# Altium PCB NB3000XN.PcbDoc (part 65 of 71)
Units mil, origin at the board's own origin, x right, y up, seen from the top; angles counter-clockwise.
Board outline 9527.56 x 6929.77 mil, 6 copper layers (Top Layer, GND+SHIELD, MidLayer1, MidLayer2, P2 - 3V3+5V0, Bottom Layer), stack 62.375 mil thick; 832 components, 1027 nets, 4655 pads, 4981 vias.
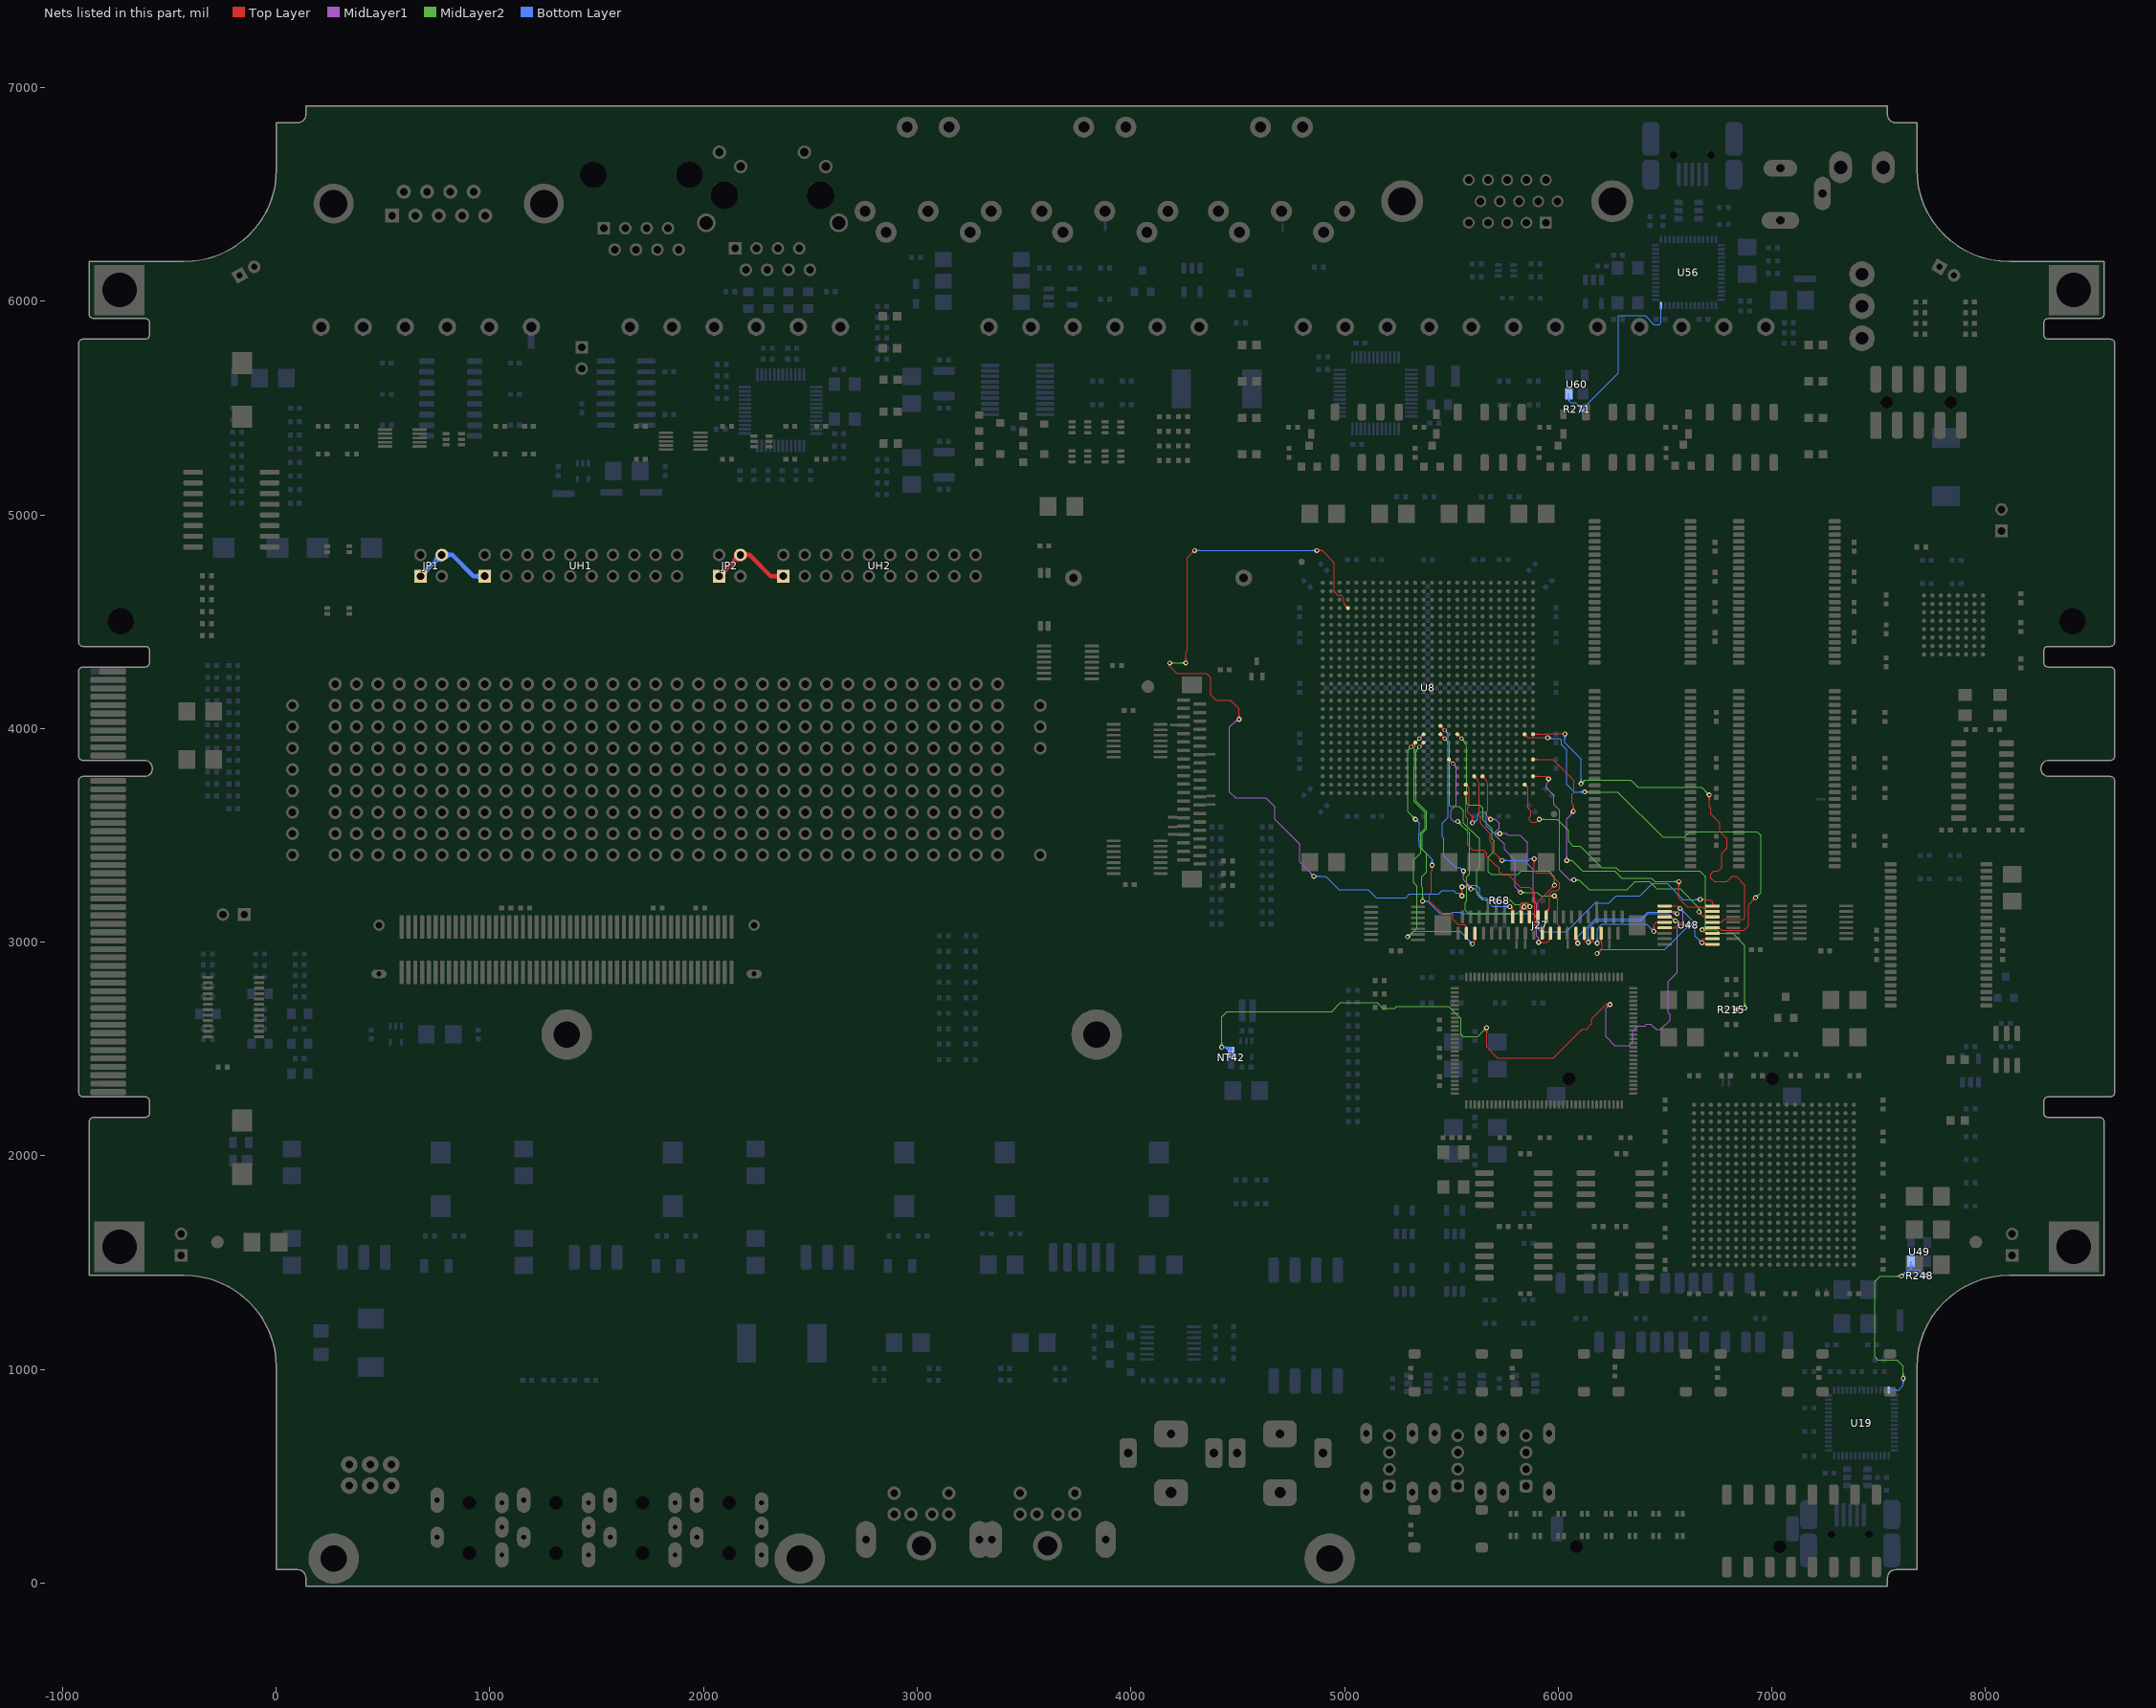
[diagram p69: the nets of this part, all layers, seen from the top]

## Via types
v1: diameter 23, hole 11.81, Top Layer to Bottom Layer, 3672 vias
v2: diameter 26, hole 11.81, Top Layer to Bottom Layer, 461 vias
v3: diameter 19, hole 11.81, Top Layer to Bottom Layer, tented both sides, 396 vias
v4: diameter 23.62, hole 11.81, Top Layer to Bottom Layer, 288 vias
v5: diameter 20, hole 11.81, Top Layer to Bottom Layer, 91 vias
v6: diameter 23, hole 11.81, Top Layer to Bottom Layer, tented both sides, 50 vias
v7: diameter 31, hole 11.81, Top Layer to Bottom Layer, 15 vias
v8: diameter 27.56, hole 11.81, Top Layer to Bottom Layer, tented both sides, 4 vias
v9: diameter 29, hole 11.81, Top Layer to Bottom Layer, 3 vias
v10: diameter 21, hole 11.81, Top Layer to Bottom Layer, 1 vias

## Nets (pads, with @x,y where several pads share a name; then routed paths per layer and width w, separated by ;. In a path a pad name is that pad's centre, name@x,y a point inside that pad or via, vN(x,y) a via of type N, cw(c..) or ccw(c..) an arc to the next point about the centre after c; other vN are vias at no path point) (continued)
TFT_IO.DB14: J27.19 U8.AD19 | length 1217.8
  Top Layer w4: U8.AD19@5606.54,3769.27 cw(c5606.54,3751.55) 5619.07,3764.08 ; U8.AD19@5613.88,3776.61 ccw(c5631.6,3776.61) 5619.07,3764.08 ; v1@5727.36,3382.37 ccw(c5704.42,3382.37) 5720.64,3398.59 ccw(c5736.86,3414.81) v1@5736.86,3391.87 ; v1@5731.36,3382.37 ccw(c5718.08,3382.37) 5727.47,3391.76 ccw(c5736.86,3401.15) v1@5736.86,3387.87 ; v1(5736.86,3382.37) 5691.19,3428.04 5691.19,3463.37 5682.86,3471.71 5682.86,3507.14 5636,3554 5636,3585.19 5630.4,3590.79 5630.4,3599 5630.4,3660 5630.4,3670 5630.4,3736.73 ccw(c5591.72,3736.73) 5619.07,3764.08 ; v1@5881.14,3383.99 cw(c5864.92,3367.77) 5887.86,3367.77 cw(c5910.79,3367.77) v1@5894.57,3383.99 ; v1@5883.97,3386.82 cw(c5874.58,3377.43) 5887.86,3377.43 cw(c5901.14,3377.43) v1@5891.75,3386.82 ; v1(5887.86,3390.71) 5887.86,3335.71 5898.52,3325.04 5956.86,3325.04 6006.86,3275.04 6006.86,3251.71 5996.86,3241.71 5973.52,3241.71 5960,3228.18 5960,3160 5944.95,3144.95 J27.19@5944.95,3118.39 ; J27.19@5946.82,3140.51 cw(c5962.05,3140.51) 5951.28,3151.28 ; J27.19@5950.82,3140.51 cw(c5975.71,3140.51) 5958.11,3158.11
  Bottom Layer w4: v1(5736.86,3382.37) 5859.96,3382.37 5868.29,3390.71 v1(5887.86,3390.71) 5887.86,3385.04 v1@5885.19,3382.37 ; v1@5740.75,3378.49 cw(c5750.14,3369.1) 5750.14,3382.37 cw(c5750.14,3395.65) v1@5740.75,3386.26 ; v1@5743.57,3375.66 cw(c5759.79,3359.44) 5759.79,3382.37 cw(c5759.79,3405.31) v1@5743.57,3389.09
TFT_IO.DB15: J27.21 U8.W17 | length 1570.7
  Top Layer w4: U8.W17@5527.8,3965.96 cw(c5527.8,3947.86) 5540.6,3960.66 cw(c5553.4,3973.46) U8.W17@5535.3,3973.46 ; U8.W17@5527.8,3966.12 cw(c5527.8,3948.4) 5540.33,3960.93 cw(c5552.86,3973.46) U8.W17@5535.14,3973.46 ; U8.W17@5527.8,3973.46 v3(5547.48,3953.78) ; J27.21@5901.42,3144.67 ccw(c5891.4,3154.69) 5905.58,3154.69 ccw(c5919.76,3154.69) J27.21@5909.73,3144.67 ; J27.21@5905.58,3118.39 5905.58,3189.43 v1(5982.86,3266.71) ; v1@5973.36,3266.71 cw(c5950.42,3266.71) 5966.64,3250.49 cw(c5982.86,3234.27) v1@5982.86,3257.21 ; v1@5977.36,3266.71 cw(c5964.08,3266.71) 5973.47,3257.32 cw(c5982.86,3247.93) v1@5982.86,3261.21 ; 5534.68,3966.58 cw(c5521.87,3953.78) 5539.98,3953.78 ccw(c5521.87,3953.78) 5534.68,3966.58 ; 5534.68,3966.58 ccw(c5547.48,3979.39) 5547.48,3961.28 cw(c5547.48,3979.39) 5534.68,3966.58
  MidLayer2 w4: v3@5546.83,3946.31 cw(c5545.25,3928.27) 5559.12,3939.91 ; v3@5554.95,3953.13 ccw(c5572.99,3951.55) 5559.12,3939.91 ; 5571.34,3680.84 5571.34,3739.1 ; v1(5982.86,3266.71) 5982.86,3307.14 5956.63,3333.37 5827.86,3333.37 5811.19,3316.71 5685.48,3316.71 5672.19,3330 5672.19,3398.04 5699.19,3425.04 5699.19,3475.04 5690.86,3483.37 5690.86,3530.02 5648.52,3572.35 5648.52,3600 5648.52,3625.71 5631.86,3642.37 5577.63,3642.37 5571.34,3648.66 5571.34,3660 5571.34,3670 5571.34,3739.1 ; 5559.12,3939.91 cw(c5529.61,3910.4) 5571.34,3910.4 5571.34,3890.9 5571.34,3816.78 5571.34,3797.36 5571.34,3739.1
TFT_IO.DB16: J27.23 U8.AB16 | length 1499.3
  Top Layer w4: U8.AB16@5488.43,3847.85 cw(c5488.43,3829.75) 5501.23,3842.55 cw(c5514.03,3855.35) U8.AB16@5495.93,3855.35 ; U8.AB16@5488.43,3848.01 cw(c5488.43,3830.29) 5500.96,3842.82 cw(c5513.49,3855.35) U8.AB16@5495.77,3855.35 ; U8.AB16@5488.43,3855.35 v3(5508.11,3835.67) ; v1@5840.19,3156.21 cw(c5840.19,3133.27) 5856.41,3149.49 cw(c5872.63,3165.71) v1@5849.69,3165.71 ; v1@5840.19,3160.21 cw(c5840.19,3146.93) 5849.58,3156.32 cw(c5858.97,3165.71) v1@5845.69,3165.71 ; v1(5840.19,3165.71) 5866.21,3139.69 J27.23@5866.21,3118.39 ; 5854.78,3151.12 ccw(c5866.21,3162.55) J27.23@5866.21,3146.39 ; 5856.76,3149.14 cw(c5848.13,3140.51) J27.23@5860.33,3140.51 ; 5495.31,3848.47 cw(c5482.5,3835.67) 5500.61,3835.67 ccw(c5482.5,3835.67) 5495.31,3848.47 ; 5495.31,3848.47 ccw(c5508.11,3861.28) 5508.11,3843.17 cw(c5508.11,3861.28) 5495.31,3848.47
  MidLayer1 w4: 5498.5,3604.17 5498.5,3601.75 ; v3@5507.46,3828.2 cw(c5505.88,3810.16) 5519.75,3821.8 cw(c5533.62,3833.44) v3@5515.58,3835.02 ; 5517.88,3565.37 cw(c5517.88,3555.43) v1@5525.68,3561.59 ; 5519.5,3822.09 cw(c5509.57,3812.16) 5523.62,3812.16 5523.62,3718.62 5523.62,3670 5523.62,3660 5523.62,3650.04 ; v1@5522.54,3559.11 ccw(c5509.63,3548.92) 5509.63,3565.37 ; v1@5522.91,3571.33 cw(c5509.63,3583.18) 5509.63,3565.37 ; 5523.52,3650.04 5523.52,3644.37 5497.5,3618.35 5497.5,3602.75 5498.5,3601.75 ; v1@5530,3565.37 5509.63,3565.37 ; 5498.5,3601.75 5498.5,3576.5 5509.63,3565.37
  MidLayer2 w4: v1@5530,3555.5 cw(c5530,3532.56) 5546.22,3548.78 cw(c5562.43,3565) v1@5539.5,3565 ; v1@5530,3559.5 cw(c5530,3546.22) 5539.39,3555.61 cw(c5548.78,3565) v1@5535.5,3565 ; v1@5531.86,3565 5531.86,3565.37 5531.48,3565 v1(5530,3565) 5585,3510 5585,3319.75 5572.5,3307.25 5572.5,3193.02 5565.19,3185.71 5565.19,3150.04 5581.86,3133.37 5807.86,3133.37 v1(5840.19,3165.71) ; v1@5830.69,3165.71 cw(c5807.76,3165.71) 5823.97,3149.49 cw(c5840.19,3133.27) v1@5840.19,3156.21 ; v1@5834.69,3165.71 cw(c5821.41,3165.71) 5830.8,3156.32 cw(c5840.19,3146.93) v1@5840.19,3160.21
TFT_IO.DB17: J27.25 U8.W15 | length 1532.1
  Top Layer w4: U8.W15@5449.06,3965.96 cw(c5449.06,3947.86) 5461.86,3960.66 cw(c5474.66,3973.46) U8.W15@5456.56,3973.46 ; U8.W15@5449.06,3966.12 cw(c5449.06,3948.4) 5461.59,3960.93 cw(c5474.12,3973.46) U8.W15@5456.4,3973.46 ; U8.W15@5449.06,3973.46 v3(5468.74,3953.78) ; J27.25@5822.76,3144.75 ccw(c5813.56,3154.31) 5826.84,3154.31 ; J27.25@5826.84,3118.39 5826.84,3154.31 ; J27.25@5830.91,3144.75 cw(c5840.11,3154.31) 5826.84,3154.31 ; 5859.36,3183.21 cw(c5849.77,3173.63) v1@5862.4,3168.71 ; 5863.69,3178.88 cw(c5856.01,3171.2) v1@5866.13,3167.25 ; v1(5867.52,3166.71) 5867.52,3175.04 5859.19,3183.37 5831.86,3183.37 5822.69,3174.21 5822.69,3158.46 5826.84,3154.31 ; 5455.94,3966.58 cw(c5443.13,3953.78) 5461.24,3953.78 ccw(c5443.13,3953.78) 5455.94,3966.58 ; 5455.94,3966.58 ccw(c5468.74,3979.39) 5468.74,3961.28 cw(c5468.74,3979.39) 5455.94,3966.58
  MidLayer2 w4: v3@5468.09,3946.31 cw(c5466.51,3928.27) 5480.38,3939.91 ; v3@5476.21,3953.13 ccw(c5494.25,3951.55) 5480.38,3939.91 ; 5492.6,3680.84 5492.6,3739.1 ; v1@5858.02,3166.71 ccw(c5835.09,3166.71) 5851.31,3182.93 ccw(c5867.52,3199.14) v1@5867.52,3176.21 ; v1@5862.02,3166.71 ccw(c5848.75,3166.71) 5858.14,3176.1 ccw(c5867.52,3185.49) v1@5867.52,3172.21 ; v1(5867.52,3166.71) 5850.86,3183.37 5830,3183.37 5823.33,3176.71 5796.86,3176.71 5773.52,3200.04 5648.52,3200.04 5619.5,3229.06 5619.5,3337.68 5631.86,3350.04 5631.86,3483.37 5556.86,3558.37 5556.86,3616.04 5556.53,3616.37 5536.9,3636 5496.6,3636 5492.6,3640 5492.6,3660 5492.6,3670 5492.6,3739.1 ; 5480.38,3939.91 cw(c5450.87,3910.4) 5492.6,3910.4 5492.6,3890.9 5492.6,3816.78 5492.6,3797.36 5492.6,3739.1
TFT_IO.IR38KRX: J27.36 U8.W13 | length 1741.3
  Top Layer w4: v3(5350.63,3953.78) U8.W13@5370.31,3973.46 ; U8.W13@5362.81,3973.46 cw(c5344.71,3973.46) 5357.51,3960.66 cw(c5370.31,3947.86) U8.W13@5370.31,3965.96 ; U8.W13@5362.97,3973.46 cw(c5345.25,3973.46) 5357.78,3960.93 cw(c5370.31,3948.4) U8.W13@5370.31,3966.12 ; v1(5598.52,2991.71) 5610.3,3003.48 J27.36@5610.3,3041.61 ; J27.36@5606.15,3015.33 cw(c5596.12,3005.31) 5610.3,3005.31 cw(c5624.48,3005.31) J27.36@5614.45,3015.33 ; 5363.43,3966.58 ccw(c5376.24,3953.78) 5358.13,3953.78 cw(c5376.24,3953.78) 5363.43,3966.58 ; 5363.43,3966.58 cw(c5350.63,3979.39) 5350.63,3961.28 ccw(c5350.63,3979.39) 5363.43,3966.58
  MidLayer2 w4: v1(5295,3025) 5298.48,3025 5298.52,3025.04 5340.19,3066.71 5340.19,3261.35 5322.52,3279.02 5322.52,3385.04 5356.7,3419.22 5356.7,3513.31 5377,3533.61 5377,3607.31 5326.77,3657.55 5326.77,3660 5326.77,3670 5326.77,3797.36 5326.77,3816.78 5326.77,3890.9 5326.77,3910.4 cw(c5368.5,3910.4) 5338.99,3939.91 ; v1@5295,3030.5 ccw(c5295,3052.19) 5310.34,3036.85 ; v1@5295,3034.5 ccw(c5295,3065.84) 5317.16,3043.68 ; v1@5304.5,3025 cw(c5319.03,3025) 5308.75,3035.27 ; v3@5343.16,3953.13 cw(c5325.12,3951.55) 5338.99,3939.91 ; v3@5351.28,3946.31 ccw(c5352.86,3928.27) 5338.99,3939.91
  Bottom Layer w4: v1(5295,3025) 5320.37,3050.37 5539.86,3050.37 v1(5598.52,2991.71) ; v1@5295,3030.5 ccw(c5295,3043.78) 5304.39,3034.39 ccw(c5313.78,3025) v1@5300.5,3025 ; v1@5295,3034.5 ccw(c5295,3057.43) 5311.22,3041.22 ccw(c5327.43,3025) v1@5304.5,3025 ; v1@5589.02,2991.71 ccw(c5566.09,2991.71) 5582.31,3007.93 ccw(c5598.52,3024.14) v1@5598.52,3001.21 ; v1@5593.02,2991.71 ccw(c5579.75,2991.71) 5589.14,3001.1 ccw(c5598.52,3010.49) v1@5598.52,2997.21
TFT_IO.IR38KTX: J27.38 U8.Y12 | length 1411.3
  Top Layer w4: v3(5311.26,3914.41) U8.Y12@5330.94,3934.09 ; U8.Y12@5323.44,3934.09 cw(c5305.34,3934.09) 5318.14,3921.29 cw(c5330.94,3908.49) U8.Y12@5330.94,3926.59 ; U8.Y12@5323.6,3934.09 cw(c5305.88,3934.09) 5318.41,3921.56 cw(c5330.94,3909.03) U8.Y12@5330.94,3926.75 ; v1(5410,3360) 5410,3334.96 5406,3330.96 5406,3232.52 5398.52,3225.04 5398.52,3191.71 5456.86,3133.37 5505.19,3133.37 5506.86,3131.71 5506.86,3107.04 5531.86,3082.04 5560.34,3082.04 5570.93,3071.45 J27.38@5570.93,3041.61 ; 5562.95,3079.44 cw(c5548.16,3064.65) J27.38@5569.06,3063.81 ; 5569.41,3072.97 cw(c5560.59,3064.15) J27.38@5573.06,3063.66 ; 5324.06,3927.21 cw(c5311.26,3940.02) 5311.26,3921.91 ccw(c5311.26,3940.02) 5324.06,3927.21 ; 5324.06,3927.21 ccw(c5336.87,3914.41) 5318.76,3914.41 cw(c5336.87,3914.41) 5324.06,3927.21
  MidLayer2 w4: 5295.75,3876.97 5295.75,3890.9 ; 5299.87,3900.83 ccw(c5309.8,3890.9) 5295.75,3890.9 ; v3@5303.79,3913.76 cw(c5285.75,3912.18) 5299.62,3900.54 cw(c5313.49,3888.9) v3@5311.91,3906.94 ; v1@5322.36,3575.04 ccw(c5299.42,3575.04) 5315.64,3591.26 ccw(c5331.86,3607.48) v1@5331.86,3584.54 ; v1@5326.36,3575.04 ccw(c5313.08,3575.04) 5322.47,3584.43 ccw(c5331.86,3593.82) v1@5331.86,3580.54 ; v1(5331.86,3575.04) 5295.75,3611.15 5295.75,3660 5295.75,3670 5295.75,3797.36 5295.75,3890.9
  Bottom Layer w4: v1@5331.86,3565.54 cw(c5331.86,3542.61) 5348.07,3558.82 cw(c5364.29,3575.04) v1@5341.36,3575.04 ; v1@5331.86,3569.54 cw(c5331.86,3556.26) 5341.25,3565.65 cw(c5350.64,3575.04) v1@5337.36,3575.04 ; v1(5331.86,3575.04) 5349.86,3557.04 5349.86,3506.14 5348.7,3504.99 5348.7,3477.23 5349.86,3476.08 5349.86,3448.37 5389.06,3409.18 5410,3388.23 v1(5410,3360) ; v1@5403.28,3366.72 ccw(c5387.06,3382.93) 5410,3382.93 ccw(c5432.93,3382.93) v1@5416.72,3366.72 ; v1@5406.11,3363.89 ccw(c5396.72,3373.28) 5410,3373.28 ccw(c5423.28,3373.28) v1@5413.89,3363.89
TFT_IO.RD: J27.16 U8.AD20 | length 1421.1
  Top Layer w4: v1@5674.02,3575.04 ccw(c5651.09,3575.04) 5667.31,3591.26 ccw(c5683.52,3607.48) v1@5683.52,3584.54 ; v1@5678.02,3575.04 ccw(c5664.75,3575.04) 5674.14,3584.43 ccw(c5683.52,3593.82) v1@5683.52,3580.54 ; v1(5683.52,3575.04) 5664.52,3594.04 5664.52,3610.46 5669.77,3615.7 5669.77,3660 5669.77,3670 5669.77,3736.73 ; v1@5981.86,3207.21 cw(c5981.86,3184.27) 5998.07,3200.49 cw(c6014.29,3216.71) v1@5991.36,3216.71 ; v1@5981.86,3211.21 cw(c5981.86,3197.93) 5991.25,3207.32 cw(c6000.64,3216.71) v1@5987.36,3216.71 ; v1(5981.86,3216.71) 5998.52,3200.04 5998.52,3083.37 6004,3077.9 ; J27.16@5999.85,3067.9 ccw(c5989.88,3077.9) 6004,3077.9 ; J27.16@6004,3041.61 6004,3077.9 ; J27.16@6008.15,3067.9 cw(c6018.12,3077.9) 6004,3077.9 ; 5658.44,3764.08 cw(c5631.09,3736.73) 5669.77,3736.73 ; 5658.44,3764.08 cw(c5631.09,3736.73) 5669.77,3736.73 ; 5658.44,3764.08 cw(c5670.97,3776.61) 5653.25,3776.61 ccw(c5670.97,3776.61) 5658.44,3764.08 ; 5658.44,3764.08 ccw(c5645.91,3751.55) 5645.91,3769.27 cw(c5645.91,3751.55) 5658.44,3764.08
  MidLayer1 w4: v1(5683.52,3575.04) 5706.86,3575.04 5723.52,3558.37 5723.52,3533.37 5706.86,3516.71 5706.86,3500.04 5748.52,3458.37 5748.52,3433.37 5798.52,3383.37 5798.52,3260.04 5823.52,3235.04 v1(5823.52,3233.37) ; v1@5687.41,3571.15 cw(c5696.8,3561.76) 5696.8,3575.04 cw(c5696.8,3588.32) v1@5687.41,3578.93 ; v1@5690.24,3568.32 cw(c5706.46,3552.11) 5706.46,3575.04 cw(c5706.46,3597.98) v1@5690.24,3581.76 ; 5806.13,3252.44 cw(c5787.07,3233.37) v1@5814.02,3233.37 ; 5810.15,3248.41 ccw(c5823.52,3261.79) v1@5823.52,3242.87 ; 5812.96,3245.61 cw(c5800.72,3233.37) v1@5818.02,3233.37
  MidLayer2 w4: v1(5823.52,3233.37) 5901.52,3233.37 5918.19,3216.71 v1(5981.86,3216.71) ; v1@5827.41,3229.49 cw(c5836.8,3220.1) 5836.8,3233.37 cw(c5836.8,3246.65) v1@5827.41,3237.26 ; v1@5830.24,3226.66 cw(c5846.46,3210.44) 5846.46,3233.37 cw(c5846.46,3256.31) v1@5830.24,3240.09 ; v1@5975.14,3209.99 ccw(c5958.92,3193.77) 5958.92,3216.71 ccw(c5958.92,3239.64) v1@5975.14,3223.43 ; v1@5977.97,3212.82 ccw(c5968.58,3203.43) 5968.58,3216.71 ccw(c5968.58,3229.99) v1@5977.97,3220.6
TFT_IO.RESET: J27.27 U8.V15 | length 1679.6
  Top Layer w4: U8.V15@5449.06,4005.33 cw(c5449.06,3987.23) 5461.86,4000.03 cw(c5474.66,4012.83) U8.V15@5456.56,4012.83 ; U8.V15@5449.06,4005.49 cw(c5449.06,3987.77) 5461.59,4000.3 cw(c5474.12,4012.83) U8.V15@5456.4,4012.83 ; U8.V15@5449.06,4012.83 v3(5468.74,3993.15) ; v1@5773.52,3157.21 cw(c5773.52,3134.27) 5789.74,3150.49 cw(c5805.96,3166.71) v1@5783.02,3166.71 ; v1@5773.52,3161.21 cw(c5773.52,3147.93) 5782.91,3157.32 cw(c5792.3,3166.71) v1@5779.02,3166.71 ; v1(5773.52,3166.71) 5790.19,3150.04 ; v1@5775.6,3164.63 cw(c5751.49,3140.51) J27.27@5785.59,3140.51 ; 5782.43,3157.8 cw(c5765.14,3140.51) J27.27@5789.59,3140.51 ; J27.27@5786.86,3146.35 ccw(c5786.49,3150.04) 5790.19,3150.04 ; J27.27@5787.47,3118.39 5787.47,3116.71 5790.19,3116.71 5790.19,3118.39 5790.19,3150.04 ; 5789.26,3150.97 cw(c5778.8,3140.51) J27.27@5793.59,3140.51 ; J27.27@5790.19,3148.12 ccw(c5795.07,3148.12) J27.27@5791.62,3144.67 ; 5455.94,4005.95 cw(c5443.13,3993.15) 5461.24,3993.15 ccw(c5443.13,3993.15) 5455.94,4005.95 ; 5455.94,4005.95 ccw(c5468.74,4018.76) 5468.74,4000.65 cw(c5468.74,4018.76) 5455.94,4005.95
  MidLayer1 w4: v1@5550.14,3326.66 cw(c5533.92,3310.44) 5556.86,3310.44 cw(c5579.79,3310.44) v1@5563.57,3326.66 ; v1@5552.97,3329.49 cw(c5543.58,3320.1) 5556.86,3320.1 cw(c5570.14,3320.1) v1@5560.75,3329.49 ; v1(5556.86,3333.37) 5556.86,3293.04 5591.52,3258.37 v1(5591.52,3249) ; 5568.68,3281.22 cw(c5536.46,3249) v1@5582.02,3249 ; 5575.51,3274.39 cw(c5550.11,3249) v1@5586.02,3249 ; 5582.33,3267.56 cw(c5563.77,3249) v1@5590.02,3249 ; 5589.16,3260.74 cw(c5577.43,3249) v1@5594.02,3249
  Bottom Layer w4: v3@5468.09,3985.68 cw(c5466.51,3967.64) 5480.38,3979.28 cw(c5494.25,3990.92) v3@5476.21,3992.5 ; 5480.13,3979.57 cw(c5470.2,3969.64) 5484.25,3969.64 5484.25,3876.1 5484.25,3670 5484.25,3660 5484.25,3584.76 5457.8,3558.31 5457.8,3491.44 5465.19,3484.05 5465.19,3406.12 5521.31,3350 5540.23,3350 v1(5556.86,3333.37) ; v1@5547.36,3333.37 ccw(c5524.42,3333.37) 5540.64,3349.59 ccw(c5556.86,3365.81) v1@5556.86,3342.87 ; v1@5551.36,3333.37 ccw(c5538.08,3333.37) 5547.47,3342.76 ccw(c5556.86,3352.15) v1@5556.86,3338.87 ; v1(5591.52,3249) 5591.52,3250.04 5608.19,3250.04 ; v1@5599.19,3254.61 ccw(c5608.19,3261.19) 5608.19,3250.04 ; v1@5600.11,3244.93 cw(c5608.19,3241.1) 5608.19,3250.04 ; v1@5766.81,3159.99 ccw(c5750.59,3143.77) 5750.59,3166.71 ccw(c5750.59,3189.64) v1@5766.81,3173.43 ; v1@5769.64,3162.82 ccw(c5760.25,3153.43) 5760.25,3166.71 ccw(c5760.25,3179.99) v1@5769.64,3170.6 ; v1(5773.52,3166.71) 5692.52,3166.71 5660.19,3199.04 5642.88,3199.04 5623.52,3218.39 5623.52,3234.71 5608.19,3250.04
TFT_IO.RS: J27.20 U8.AF18 | length 971.7
  Top Layer w4: U8.AF18@5561.86,3692.57 cw(c5549.06,3679.77) 5567.17,3679.77 cw(c5585.27,3679.77) U8.AF18@5572.47,3692.57 ; U8.AF18@5561.97,3692.68 cw(c5549.44,3680.15) 5567.17,3680.15 cw(c5584.89,3680.15) U8.AF18@5572.36,3692.68 ; U8.AF18@5567.17,3697.87 5567.17,3670 5567.17,3660 5567.17,3586.59 5576.81,3576.94 5576.81,3455.34 5599.61,3432.54 5649.36,3432.54 5649.52,3432.37 5665.19,3416.71 5665.19,3401.71 5705.86,3361.04 5710.19,3361.04 5723.52,3347.71 5723.52,3330 5736.82,3316.71 5765.19,3316.71 5823.52,3258.37 5865.19,3258.37 5890.19,3233.37 5890.19,3080.71 5893.19,3077.71 5904.19,3077.71 5923.52,3058.37 5923.52,3041.71 5925.26,3041.71 J27.20@5925.26,3041.61 ; 5907.74,3074.16 ccw(c5920.1,3086.51) J27.20@5923.96,3069.47 ; 5912.87,3069.03 ccw(c5922,3078.15) J27.20@5924.85,3065.57
TFT_IO.WR: J27.18 U8.AE18 | length 1481.3
  Top Layer w4: U8.AE18@5567.17,3729.9 cw(c5567.17,3712.17) 5579.7,3724.71 ; U8.AE18@5574.51,3737.24 ccw(c5592.23,3737.24) 5579.7,3724.71 ; v1@5590.19,3558.37 v1(5598.52,3558.37) 5598.52,3586 5576.69,3607.83 5576.69,3631.96 5582.67,3637.94 5582.67,3660 5582.67,3670 5582.67,3717.53 ccw(c5572.52,3717.53) 5579.7,3724.71 ; v1@5591.81,3565.09 ccw(c5575.59,3581.31) 5598.52,3581.31 ccw(c5621.46,3581.31) v1@5605.24,3565.09 ; v1@5594.64,3562.26 ccw(c5585.25,3571.65) 5598.52,3571.65 ccw(c5611.8,3571.65) v1@5602.41,3562.26 ; v1(5907.86,2999.04) 5947.52,2999.04 5965.19,3016.71 5965.19,3041.61 5965.19,3041.71 5964.63,3041.71 J27.18@5964.63,3041.61 ; v1@5911.75,2995.15 cw(c5921.14,2985.76) 5921.14,2999.04 cw(c5921.14,3012.32) v1@5911.75,3002.93 ; v1@5914.57,2992.32 cw(c5930.79,2976.11) 5930.79,2999.04 cw(c5930.79,3021.98) v1@5914.57,3005.76 ; 5952.24,3003.76 ccw(c5936.52,3019.49) J27.18@5958.76,3019.49 ; 5959.07,3010.59 ccw(c5950.17,3019.49) J27.18@5962.76,3019.49 ; J27.18@5960.3,3011.82 cw(c5964.63,3007.49) J27.18@5964.63,3013.61
  MidLayer1 w4: v1(5726.52,3508.37) 5727.52,3509.37 5756.86,3509.37 5765.19,3501.04 5820.52,3501.04 5856.86,3464.71 5856.86,3395 5856.86,3366.83 5882.86,3340.83 5882.86,3324.04 5882.86,3315 5882.86,3194.69 5898.19,3179.36 5898.19,3027.75 5907.86,3018.08 ; v1@5902.14,3006.63 ccw(c5893.53,3018.08) 5907.86,3018.08 ; v1(5907.86,2999.04) 5907.86,3018.08 ; v1@5913.57,3006.63 cw(c5922.18,3018.08) 5907.86,3018.08
  Bottom Layer w4: v1(5598.52,3558.37) 5606.86,3558.37 5623.52,3575.04 ; v1@5598.79,3559.85 ccw(c5601.57,3575.34) 5612.7,3564.21 ; v1@5599.5,3563.79 ccw(c5603.22,3584.52) 5618.11,3569.63 ; v1@5600.2,3567.73 ccw(c5604.86,3593.7) 5623.52,3575.04 ; v1@5719.81,3501.66 ccw(c5703.59,3485.44) 5703.59,3508.37 ccw(c5703.59,3531.31) v1@5719.81,3515.09 ; v1@5722.64,3504.49 ccw(c5713.25,3495.1) 5713.25,3508.37 ccw(c5713.25,3521.65) v1@5722.64,3512.26 ; v1@5724.86,3500.04 5726.52,3501.71 v1(5726.52,3508.37) 5701.63,3508.37 5664.96,3545.04 5664.86,3545.04 5664.86,3606.71 5663.19,3608.37 5631.86,3608.37 5623.52,3600.04 5623.52,3575.04
TFT_TOUCH.X+: J27.12 U48.2 | length 995.1
  Top Layer w4: J27.12@6078.59,3015.33 cw(c6068.56,3005.31) 6082.74,3005.31 cw(c6096.92,3005.31) J27.12@6086.9,3015.33 ; 6082.74,3010.54 ccw(c6106.69,3010.54) v1@6089.76,2993.61 ; J27.12@6082.74,3020.2 ccw(c6116.35,3020.2) v1@6092.58,2996.44 ; J27.12@6082.74,3029.85 ccw(c6126,3029.85) v1@6095.41,2999.26 ; J27.12@6082.74,3039.51 ccw(c6135.66,3039.51) v1@6098.24,3002.09 ; J27.12@6082.74,3041.61 6082.74,3004.16 v1(6091.52,2995.37) ; U48.2@6497.8,3143.98 6546.26,3143.98 v1(6556.86,3133.37) ; U48.2@6527.83,3140.52 cw(c6536.17,3132.17) 6536.17,3143.98 cw(c6536.18,3155.78) U48.2@6527.83,3147.43
  Bottom Layer w4: v1@6084.81,3002.09 ccw(c6068.59,3018.31) 6091.52,3018.31 ccw(c6114.46,3018.31) v1@6098.24,3002.09 ; v1@6087.64,2999.26 ccw(c6078.25,3008.65) 6091.52,3008.65 ccw(c6104.8,3008.65) v1@6095.41,2999.26 ; v1(6091.52,2995.37) 6091.52,3026.06 6173.84,3108.37 6384.84,3108.37 6418.17,3141.71 6445,3141.71 6548.52,3141.71 v1(6556.86,3133.37) ; 6513.8,3141.71 cw(c6513.8,3090.32) v1@6550.14,3126.66 ; 6523.46,3141.71 cw(c6523.46,3099.98) v1@6552.97,3129.49 ; 6533.12,3141.71 cw(c6533.12,3109.64) v1@6555.8,3132.31 ; 6542.78,3141.71 cw(c6542.78,3119.29) v1@6558.62,3135.14
TFT_TOUCH.X-: J27.8 U48.4 | length 714.7
  Top Layer w4: J27.8@6157.33,3015.33 cw(c6147.3,3005.31) 6161.48,3005.31 cw(c6175.66,3005.31) J27.8@6165.64,3015.33 ; J27.8@6161.48,3041.61 6161.48,3003.37 6169.48,2995.37 v1(6183.19,2995.37) ; v1@6441.81,3056.76 ccw(c6425.59,3072.98) 6448.52,3072.98 ccw(c6471.46,3072.98) v1@6455.24,3056.76 ; v1@6444.64,3053.93 ccw(c6435.25,3063.32) 6448.52,3063.32 ccw(c6461.8,3063.32) v1@6452.41,3053.93 ; v1(6448.52,3050.04) 6448.52,3081.37 6459.94,3092.79 ; U48.4@6467.65,3089.45 ccw(c6459.94,3082.24) 6459.94,3092.79 ; U48.4@6467.65,3096.14 cw(c6459.94,3103.35) 6459.94,3092.79 ; U48.4@6497.8,3092.8 6459.94,3092.79
  Bottom Layer w4: v1@6176.47,3002.09 ccw(c6160.26,3018.31) 6183.19,3018.31 ccw(c6206.13,3018.31) v1@6189.91,3002.09 ; v1@6179.3,2999.26 ccw(c6169.91,3008.65) 6183.19,3008.65 ccw(c6196.47,3008.65) v1@6187.08,2999.26 ; v1(6183.19,2995.37) 6183.19,3063.19 6204.04,3084.04 6414.52,3084.04 v1(6448.52,3050.04) ; v1@6439.02,3050.04 ccw(c6416.09,3050.04) 6432.31,3066.26 ccw(c6448.52,3082.48) v1@6448.52,3059.54 ; v1@6443.02,3050.04 ccw(c6429.75,3050.04) 6439.14,3059.43 ccw(c6448.52,3068.82) v1@6448.52,3055.54
TFT_TOUCH.Y+: J27.10 U48.3 | length 846.7
  Top Layer w4: J27.10@6118.8,3014.63 cw(c6114.54,3008.38) 6122.11,3008.38 ; J27.10@6122.11,3041.61 6122.11,3008.37 ; J27.10@6125.42,3014.63 ccw(c6129.69,3008.38) 6122.11,3008.38 ; v1(6141.52,3000.04) 6130.45,3000.04 6122.11,3008.37 ; U48.3@6497.8,3118.39 6530.18,3118.39 v1(6548.52,3100.04) ; U48.3@6524.37,3113.5 cw(c6524.37,3087.67) v1@6542.63,3105.93 ; U48.3@6524.37,3117.5 cw(c6524.37,3101.32) 6535.81,3112.76 ; v1@6539.02,3100.04 ccw(c6516.09,3100.04) 6532.31,3116.26 ccw(c6548.52,3132.48) v1@6548.52,3109.54 ; v1@6543.02,3100.04 ccw(c6529.75,3100.04) 6539.14,3109.43 ccw(c6548.52,3118.82) v1@6548.52,3105.54
  Bottom Layer w4: v1@6134.81,3006.76 ccw(c6118.59,3022.98) 6141.52,3022.98 ccw(c6164.46,3022.98) v1@6148.24,3006.76 ; v1@6137.64,3003.93 ccw(c6128.25,3013.32) 6141.52,3013.32 ccw(c6154.8,3013.32) v1@6145.41,3003.93 ; v1(6141.52,3000.04) 6141.52,3064.75 6176.82,3100.04 6387.82,3100.04 6421.15,3133.37 6465,3133.37 6515.19,3133.37 v1(6548.52,3100.04) ; v1@6539.02,3100.04 ccw(c6516.09,3100.04) 6532.31,3116.26 ccw(c6548.52,3132.48) v1@6548.52,3109.54 ; v1@6543.02,3100.04 ccw(c6529.75,3100.04) 6539.14,3109.43 ccw(c6548.52,3118.82) v1@6548.52,3105.54
TFT_TOUCH.Y-: J27.6 U48.5 | length 989.2
  Top Layer w4: v1(6181.86,2947.37) 6206.86,2972.37 6206.86,2995 6200.85,3001 J27.6@6200.85,3041.61 ; v1@6181.86,2952.87 ccw(c6181.86,2966.15) 6191.25,2956.76 ccw(c6200.64,2947.37) v1@6187.36,2947.37 ; v1@6181.86,2956.87 ccw(c6181.86,2979.81) 6198.07,2963.59 ccw(c6214.29,2947.37) v1@6191.36,2947.37 ; J27.6@6196.7,3015.33 cw(c6186.67,3005.31) 6200.85,3005.31 cw(c6215.03,3005.31) J27.6@6205.01,3015.33 ; U48.5@6497.8,3067.2 6543.67,3067.2 6559.84,3083.37 v1(6615.19,3083.37) ; U48.5@6527.83,3063.75 cw(c6536.17,3055.4) 6536.17,3067.2 cw(c6536.17,3079.01) U48.5@6527.83,3070.66 ; v1@6608.47,3076.66 ccw(c6592.26,3060.44) 6592.26,3083.37 ccw(c6592.26,3106.31) v1@6608.47,3090.09 ; v1@6611.3,3079.49 ccw(c6601.91,3070.1) 6601.91,3083.37 ccw(c6601.91,3096.65) v1@6611.3,3087.26
  Bottom Layer w4: v1(6181.86,2947.37) 6201.19,2966.71 6498.52,2966.71 v1(6615.19,3083.37) ; v1@6181.86,2952.87 ccw(c6181.86,2966.15) 6191.25,2956.76 ccw(c6200.64,2947.37) v1@6187.36,2947.37 ; v1@6181.86,2956.87 ccw(c6181.86,2979.81) 6198.07,2963.59 ccw(c6214.29,2947.37) v1@6191.36,2947.37 ; v1@6605.69,3083.37 cw(c6582.76,3083.37) 6598.97,3067.16 cw(c6615.19,3050.94) v1@6615.19,3073.87 ; v1@6609.69,3083.37 cw(c6596.41,3083.37) 6605.8,3073.99 cw(c6615.19,3064.6) v1@6615.19,3077.87
TFT_TSC.BUSY: U8.W26 U48.13 | length 2439.4
  Top Layer w4: U8.W26@5882.13,3973.46 5910,3973.46 5920,3973.46 5924.74,3973.46 5938.61,3973.46 5940.19,3975.04 v1(6031.86,3975.04) ; U8.W26@5887.32,3968.27 cw(c5899.85,3955.74) 5899.85,3973.46 cw(c5899.85,3991.19) U8.W26@5887.32,3978.66 ; U8.W26@5887.43,3968.16 cw(c5900.23,3955.36) 5900.23,3973.46 cw(c5900.23,3991.57) U8.W26@5887.43,3978.77 ; v1@6025.14,3968.32 ccw(c6008.92,3952.11) 6008.92,3975.04 ccw(c6008.92,3997.98) v1@6025.14,3981.76 ; v1@6027.97,3971.15 ccw(c6018.58,3961.76) 6018.58,3975.04 ccw(c6018.58,3988.32) v1@6027.97,3978.93 ; v1@6700.14,3683.32 cw(c6683.92,3667.11) 6706.86,3667.11 cw(c6729.79,3667.11) v1@6713.57,3683.32 ; v1@6702.97,3686.15 cw(c6693.58,3676.76) 6706.86,3676.76 cw(c6720.14,3676.76) v1@6710.75,3686.15 ; v1(6706.86,3690.04) 6706.86,3634.33 6715.19,3626 6715.19,3600.04 6756.86,3558.37 6756.86,3516.71 6790.19,3483.37 6790.19,3441.71 6765.19,3416.71 6765.19,3350.04 6748.52,3333.37 6728.52,3333.37 6715.19,3320.04 6715.19,3300.04 6731.86,3283.37 6790.19,3283.37 6815.19,3308.37 6831.86,3308.37 6873.52,3266.71 6873.52,3113.52 6866.71,3106.71 6777.58,3106.71 6763.67,3092.79 U48.13@6722.2,3092.8 ; U48.13@6752.24,3089.34 cw(c6760.58,3080.99) 6760.58,3092.79 cw(c6760.59,3104.6) U48.13@6752.24,3096.25
  MidLayer2 w4: v1(6106.86,3741.71) 6123.52,3758.37 6341.19,3758.37 6374.52,3725.04 6671.86,3725.04 v1(6706.86,3690.04) ; v1@6106.86,3747.21 ccw(c6106.86,3760.49) 6116.25,3751.1 ccw(c6125.64,3741.71) v1@6112.36,3741.71 ; v1@6106.86,3751.21 ccw(c6106.86,3774.14) 6123.07,3757.93 ccw(c6139.29,3741.71) v1@6116.36,3741.71 ; v1@6697.36,3690.04 ccw(c6674.42,3690.04) 6690.64,3706.26 ccw(c6706.86,3722.48) v1@6706.86,3699.54 ; v1@6701.36,3690.04 ccw(c6688.08,3690.04) 6697.47,3699.43 ccw(c6706.86,3708.82) v1@6706.86,3695.54
  Bottom Layer w4: v1@6025.14,3968.32 cw(c6008.92,3952.11) 6031.86,3952.11 cw(c6054.79,3952.11) v1@6038.57,3968.32 ; v1@6027.97,3971.15 cw(c6018.58,3961.76) 6031.86,3961.76 cw(c6045.14,3961.76) v1@6035.75,3971.15 ; v1(6031.86,3975.04) 6031.86,3933.37 6106.86,3858.37 v1(6106.86,3741.71) ; v1@6100.14,3748.43 ccw(c6083.92,3764.64) 6106.86,3764.64 ccw(c6129.79,3764.64) v1@6113.57,3748.43 ; v1@6102.97,3745.6 ccw(c6093.58,3754.99) 6106.86,3754.99 ccw(c6120.14,3754.99) v1@6110.75,3745.6
TFT_TSC.CLK: U8.Y13 U48.16 | length 2771.2
  Top Layer w4: v3(5350.63,3914.41) U8.Y13@5370.31,3934.09 ; U8.Y13@5362.81,3934.09 cw(c5344.71,3934.09) 5357.51,3921.29 cw(c5370.31,3908.49) U8.Y13@5370.31,3926.59 ; U8.Y13@5362.97,3934.09 cw(c5345.25,3934.09) 5357.78,3921.56 cw(c5370.31,3909.03) U8.Y13@5370.31,3926.75 ; v1(6665.19,3200.04) 6709.96,3200.04 6722.2,3187.8 U48.16@6722.2,3169.57 ; v1@6669.08,3196.15 cw(c6678.47,3186.76) 6678.47,3200.04 cw(c6678.47,3213.32) v1@6669.08,3203.93 ; v1@6671.91,3193.32 cw(c6688.13,3177.11) 6688.13,3200.04 cw(c6688.13,3222.98) v1@6671.91,3206.76 ; U48.16@6718.75,3173.02 ccw(c6710.4,3181.37) 6722.2,3181.37 ccw(c6734.01,3181.37) U48.16@6725.66,3173.02 ; 5363.43,3927.21 cw(c5350.63,3940.02) 5350.63,3921.91 ccw(c5350.63,3940.02) 5363.43,3927.21 ; 5363.43,3927.21 ccw(c5376.24,3914.41) 5358.13,3914.41 cw(c5376.24,3914.41) 5363.43,3927.21
  MidLayer2 w4: 5335.12,3660.51 5385,3610.63 ; 5335.12,3661 5335.12,3671 ; 5335.12,3670 5335.12,3797.36 5335.12,3890.9 cw(c5349.17,3890.9) 5339.24,3900.83 ; v3@5343.16,3913.76 cw(c5325.12,3912.18) 5338.99,3900.54 cw(c5352.86,3888.9) v3@5351.28,3906.94 ; v1@5358.47,3198.43 ccw(c5342.26,3214.64) 5365.19,3214.64 ccw(c5388.13,3214.64) v1@5371.91,3198.43 ; v1@5361.3,3195.6 ccw(c5351.91,3204.99) 5365.19,3204.99 ccw(c5378.47,3204.99) v1@5369.08,3195.6 ; v1(5365.19,3191.71) 5365.19,3257.31 5362.5,3260 5362.5,3306.35 5384.5,3328.35 5384.5,3415.06 5364.7,3434.86 5364.7,3510 5385,3530.3 5385,3610.63 ; 5385,3611.31 5385,3610.63
  Bottom Layer w4: v1(5365.19,3191.71) 5389.52,3191.71 5447.86,3133.37 5497.52,3133.37 5505.86,3141.71 5541.19,3141.71 5549.86,3133.04 5882.19,3133.04 5906.86,3108.37 5906.86,3063.37 5920.19,3050.04 6038.9,3050.04 6172.23,3183.37 6237.21,3183.37 6270.54,3216.71 6381.86,3216.71 6440.52,3275.37 6510,3275.37 6585.33,3200.04 v1(6665.19,3200.04) ; v1@5369.08,3187.82 cw(c5378.47,3178.43) 5378.47,3191.71 cw(c5378.47,3204.99) v1@5369.08,3195.6 ; v1@5371.91,3184.99 cw(c5388.13,3168.77) 5388.13,3191.71 cw(c5388.13,3214.64) v1@5371.91,3198.43 ; v1@6658.47,3193.32 ccw(c6642.26,3177.11) 6642.26,3200.04 ccw(c6642.26,3222.98) v1@6658.47,3206.76 ; v1@6661.3,3196.15 ccw(c6651.91,3186.76) 6651.91,3200.04 ccw(c6651.91,3213.32) v1@6661.3,3203.93
TFT_TSC.CS_N: U8.AB26 U48.15 | length 1882
  Top Layer w4: U8.AB26@5882.13,3855.35 5910,3855.35 5920,3855.35 5975.25,3855.35 6044.7,3785.91 6073.52,3757.08 6073.52,3700.04 6065.19,3691.71 6065.19,3649.81 ; U8.AB26@5887.32,3850.16 cw(c5899.85,3837.63) 5899.85,3855.35 cw(c5899.85,3873.08) U8.AB26@5887.32,3860.55 ; U8.AB26@5887.43,3850.05 cw(c5900.23,3837.25) 5900.23,3855.35 cw(c5900.23,3873.46) U8.AB26@5887.43,3860.66 ; v1@6064.14,3619.43 ccw(c6047.92,3635.64) 6070.86,3635.64 ccw(c6093.79,3635.64) v1@6077.57,3619.43 ; 6065,3650 6065.19,3649.81 ; v1@6066.97,3616.6 ccw(c6057.58,3625.99) 6070.86,3625.99 ccw(c6084.14,3625.99) v1@6074.75,3616.6 ; v1(6070.86,3612.71) 6070.86,3644.14 6065.19,3649.81 ; v1@6558.47,3276.66 cw(c6542.26,3260.44) 6565.19,3260.44 cw(c6588.13,3260.44) v1@6571.91,3276.66 ; v1@6561.3,3279.49 cw(c6551.91,3270.1) 6565.19,3270.1 cw(c6578.47,3270.1) v1@6569.08,3279.49 ; v1(6565.19,3283.37) 6565.19,3204.81 6605,3165 6675.23,3165 6696.26,3143.98 U48.15@6722.2,3143.98 ; 6686.84,3153.39 cw(c6677.43,3143.98) U48.15@6690.74,3143.98 ; 6688.35,3151.88 ccw(c6695.63,3159.16) U48.15@6695.63,3148.87
  MidLayer1 w4: v1@6033.47,3389.09 ccw(c6017.26,3405.31) 6040.19,3405.31 ccw(c6063.13,3405.31) v1@6046.91,3389.09 ; v1@6036.3,3386.26 ccw(c6026.91,3395.65) 6040.19,3395.65 ccw(c6053.47,3395.65) v1@6044.08,3386.26 ; v1(6040.19,3382.37) 6040.19,3576.71 6071.86,3608.37 6071.86,3611.71 v1(6070.86,3612.71) ; 6050.87,3587.39 ccw(c6025.55,3612.71) v1@6061.36,3612.71 ; 6057.7,3594.21 ccw(c6039.2,3612.71) v1@6065.36,3612.71 ; 6063.74,3600.26 cw(c6070.86,3593.15) v1@6070.86,3603.21 ; 6064.53,3601.04 ccw(c6052.86,3612.71) v1@6069.36,3612.71
  MidLayer2 w4: v1(6040.19,3382.37) 6065.19,3382.37 6114.19,3333.37 6264.58,3333.37 6297.92,3300.04 6435.86,3300.04 6452.52,3283.37 v1(6565.19,3283.37) ; v1@6044.08,3378.49 cw(c6053.47,3369.1) 6053.47,3382.37 cw(c6053.47,3395.65) v1@6044.08,3386.26 ; v1@6046.91,3375.66 cw(c6063.13,3359.44) 6063.13,3382.37 cw(c6063.13,3405.31) v1@6046.91,3389.09 ; v1@6558.47,3276.66 ccw(c6542.26,3260.44) 6542.26,3283.37 ccw(c6542.26,3306.31) v1@6558.47,3290.09 ; v1@6561.3,3279.49 ccw(c6551.91,3270.1) 6551.91,3283.37 ccw(c6551.91,3296.65) v1@6561.3,3287.26
TFT_TSC.DIN: U8.AD26 U48.14 | length 1658.2
  Top Layer w4: U8.AD26@5882.13,3776.61 5910,3776.61 5920,3776.61 5943.39,3776.61 v1(5955,3765) ; U8.AD26@5887.32,3771.42 cw(c5899.85,3758.89) 5899.85,3776.61 cw(c5899.85,3794.34) U8.AD26@5887.32,3781.81 ; U8.AD26@5887.43,3771.31 cw(c5900.23,3758.51) 5900.23,3776.61 cw(c5900.23,3794.72) U8.AD26@5887.43,3781.92 ; v1@6658.86,3132.21 cw(c6658.86,3114.1) 6671.66,3126.9 ; v1(6658.86,3141.71) 6658.86,3139.71 6680.18,3118.39 U48.14@6722.2,3118.39 ; v1@6664.36,3141.71 ccw(c6682.46,3141.71) 6669.66,3128.9 ; v1@6668.36,3141.71 ccw(c6696.12,3141.71) 6676.49,3122.08 ; U48.14@6692.17,3114.93 ccw(c6683.83,3106.58) 6683.83,3118.39 ccw(c6683.83,3130.19) U48.14@6692.17,3121.84
  MidLayer1 w4: v1(5955,3765) 5955,3751.43 5946.19,3742.62 5946.19,3720.71 5948.52,3718.37 5979.19,3687.71 5979.19,3644.37 6006.86,3616.71 6006.86,3338.14 6053.29,3291.71 ; v1@6066.21,3285.64 ccw(c6053.29,3274.92) 6053.29,3291.71 ; v1@6066.21,3297.78 cw(c6053.29,3308.5) 6053.29,3291.71 ; v1@6069.29,3288.2 ccw(c6061.81,3281.99) 6061.81,3291.71 ccw(c6061.81,3301.43) v1@6069.29,3295.22 ; v1(6073.52,3291.71) 6053.29,3291.71
  MidLayer2 w4: v1(6073.52,3291.71) 6098.52,3291.71 6144.43,3245.8 6322.26,3245.8 6360.17,3283.71 6428.54,3283.71 6461.88,3250.37 6570.21,3250.37 6658.86,3161.73 ; v1@6077.41,3287.82 cw(c6086.8,3278.43) 6086.8,3291.71 cw(c6086.8,3304.99) v1@6077.41,3295.6 ; v1@6080.24,3284.99 cw(c6096.46,3268.77) 6096.46,3291.71 cw(c6096.46,3314.64) v1@6080.24,3298.43 ; v1@6652.85,3149.07 ccw(c6642.52,3161.73) 6658.86,3161.73 ; v1@6655.38,3145.97 ccw(c6649.4,3153.3) 6658.86,3153.3 ccw(c6668.32,3153.3) v1@6662.34,3145.97 ; v1(6658.86,3141.71) 6658.86,3161.73 ; v1@6664.86,3149.07 cw(c6675.2,3161.73) 6658.86,3161.73
TFT_TSC.DOUT: U8.W25 U48.12 | length 2418.5
  Top Layer w4: U8.W25@5842.76,3966.12 cw(c5842.76,3948.4) 5855.29,3960.93 ; U8.W25@5850.1,3973.46 ccw(c5867.83,3973.46) 5855.29,3960.93 ; v1(5950.52,3957.37) 5949.52,3958.37 5949.11,3957.96 5920,3957.96 5910,3957.96 5862.47,3957.96 cw(c5862.47,3968.11) 5855.29,3960.93 ; U48.12@6722.2,3067.2 6752.8,3067.2 6765.29,3054.71 6869.86,3054.71 6890.19,3075.04 6890.19,3175.04 v1(6923.52,3208.37) ; U48.12@6748.78,3062.32 cw(c6748.78,3040.82) 6763.98,3056.02 ; U48.12@6748.78,3066.32 cw(c6748.78,3054.47) 6757.15,3062.85 ; v1@6914.02,3208.37 cw(c6891.09,3208.37) 6907.31,3192.16 cw(c6923.52,3175.94) v1@6923.52,3198.87 ; v1@6918.02,3208.37 cw(c6904.75,3208.37) 6914.14,3198.99 cw(c6923.52,3189.6) v1@6923.52,3202.87
  MidLayer2 w4: v1(6123.52,3703.71) 6278.19,3703.71 6490.19,3491.71 6590.19,3491.71 6615.19,3516.71 6931.86,3516.71 6948.52,3500.04 6948.52,3233.37 v1(6923.52,3208.37) ; v1@6127.41,3699.82 cw(c6136.8,3690.43) 6136.8,3703.71 cw(c6136.8,3716.99) v1@6127.41,3707.6 ; v1@6130.24,3696.99 cw(c6146.46,3680.77) 6146.46,3703.71 cw(c6146.46,3726.64) v1@6130.24,3710.43 ; v1@6923.52,3213.87 ccw(c6923.52,3227.15) 6932.91,3217.76 ccw(c6942.3,3208.37) v1@6929.02,3208.37 ; v1@6923.52,3217.87 ccw(c6923.52,3240.81) 6939.74,3224.59 ccw(c6955.96,3208.37) v1@6933.02,3208.37
  Bottom Layer w4: v1(5950.52,3957.37) 5953.86,3957.37 5956.86,3954.37 6006.86,3954.37 6015.19,3946.04 6015.19,3925.04 6040.19,3900.04 6040.81,3899.42 6040.81,3829.38 6040.81,3739.19 ; v1@5954.41,3961.26 ccw(c5971.04,3977.9) 5971.04,3954.37 ; v1@5957.24,3950.66 cw(c5966.22,3941.68) 5966.22,3954.37 ; v1@5957.24,3964.09 ccw(c5980.7,3987.55) 5980.7,3954.37 ; 6040.81,3780 6040.81,3739.19 ; v1@6116.81,3696.99 ccw(c6100.59,3680.77) 6100.59,3703.71 ccw(c6100.59,3726.64) v1@6116.81,3710.43 ; v1@6119.64,3699.82 ccw(c6110.25,3690.43) 6110.25,3703.71 ccw(c6110.25,3716.99) v1@6119.64,3707.6 ; v1(6123.52,3703.71) 6076.29,3703.71 6040.81,3739.19
TFT_TSC.TFT_INT: R215.2 U8.AE25 U48.11 | length 2453.6
  Top Layer w4: v1(5911.52,3575.04) 5897.36,3560.87 5875.28,3560.87 5865.02,3571.13 5865.02,3585.62 5872.81,3593.41 5872.81,3612.38 5858.26,3626.92 5858.26,3660 5858.26,3670 5858.26,3717.53 ; v1@6673.52,3048.87 cw(c6673.52,3025.94) 6689.74,3042.16 cw(c6705.96,3058.37) v1@6683.02,3058.37 ; v1@6673.52,3052.87 cw(c6673.52,3039.6) 6682.91,3048.99 cw(c6692.3,3058.37) v1@6679.02,3058.37 ; v1(6673.52,3058.37) 6690.28,3041.61 U48.11@6722.2,3041.61 ; v1@6678.16,3053.74 ccw(c6695.63,3071.21) U48.11@6695.63,3046.5 ; 6684.99,3046.91 ccw(c6695.63,3057.56) U48.11@6695.63,3042.5 ; R215.2@6831.18,2685 6858.48,2685 6865.19,2691.71 v1(6873.52,2691.71) ; R215.2@6834.94,2681.24 cw(c6844.02,2672.16) 6844.02,2685 cw(c6844.02,2697.84) R215.2@6834.94,2688.76 ; R215.2@6837.77,2678.41 cw(c6853.68,2662.5) 6853.68,2685 cw(c6853.68,2707.5) R215.2@6837.77,2691.59 ; 5855.29,3724.71 cw(c5848.11,3717.53) 5858.26,3717.53 ; 5855.29,3724.71 cw(c5848.11,3717.53) 5858.26,3717.53 ; 5855.29,3724.71 ccw(c5842.76,3712.17) 5842.76,3729.9 cw(c5842.76,3712.17) 5855.29,3724.71 ; 5855.29,3724.71 cw(c5867.83,3737.24) 5850.1,3737.24 ccw(c5867.83,3737.24) 5855.29,3724.71
  MidLayer2 w4: v1(5911.52,3575.04) 5995.54,3575.04 6048.52,3522.06 6048.52,3471.48 6069.63,3450.37 6103.54,3450.37 6203.88,3350.04 6270.54,3350.04 6286.54,3334.04 6645,3334.04 6656.86,3334.04 6661.88,3334.04 6690.19,3305.73 6690.19,3300.71 6690.19,3285 6690.19,3075.04 v1(6673.52,3058.37) 6740.86,3058.37 6757.52,3041.71 6816.86,3041.71 6873.52,2985.04 v1(6873.52,2691.71) ; v1@5915.41,3571.15 cw(c5924.8,3561.76) 5924.8,3575.04 cw(c5924.8,3588.32) v1@5915.41,3578.93 ; v1@5918.24,3568.32 cw(c5934.46,3552.11) 5934.46,3575.04 cw(c5934.46,3597.98) v1@5918.24,3581.76 ; v1@6673.52,3063.87 ccw(c6673.52,3077.15) 6682.91,3067.76 ccw(c6692.3,3058.37) v1@6679.02,3058.37 ; v1@6673.52,3067.87 ccw(c6673.52,3090.81) 6689.74,3074.59 ccw(c6705.96,3058.37) v1@6683.02,3058.37 ; v1@6677.41,3054.49 cw(c6686.8,3045.1) 6686.8,3058.37 cw(c6686.8,3071.65) v1@6677.41,3062.26 ; v1@6680.24,3051.66 cw(c6696.46,3035.44) 6696.46,3058.37 cw(c6696.46,3081.31) v1@6680.24,3065.09 ; v1@6866.81,2698.43 ccw(c6850.59,2714.64) 6873.52,2714.64 ccw(c6896.46,2714.64) v1@6880.24,2698.43 ; v1@6869.64,2695.6 ccw(c6860.25,2704.99) 6873.52,2704.99 ccw(c6886.8,2704.99) v1@6877.41,2695.6
TMS: R68.2 U8.D4 | length 4995.7
  Top Layer w4: v1@4188.52,4307.04 v1(4181.86,4307.04) 4181.86,4291.52 4215,4258.37 4353.88,4258.37 4373.86,4238.39 4373.86,4158.04 4398.52,4133.37 4465.19,4133.37 4506.86,4091.71 v1(4506.86,4043.37) ; v1@4250.14,4313.76 ccw(c4233.92,4329.98) 4256.86,4329.98 ccw(c4279.79,4329.98) v1@4263.57,4313.76 ; v1@4252.97,4310.93 ccw(c4243.58,4320.32) 4256.86,4320.32 ccw(c4270.14,4320.32) v1@4260.75,4310.93 ; v1(4256.86,4307.04) 4256.86,4356.67 4265.19,4365 4265.19,4800.04 v1(4298.52,4833.37) ; v1@4289.02,4833.37 cw(c4266.09,4833.37) 4282.31,4817.16 cw(c4298.52,4800.94) v1@4298.52,4823.87 ; v1@4293.02,4833.37 cw(c4279.75,4833.37) 4289.14,4823.99 cw(c4298.52,4814.6) v1@4298.52,4827.87 ; v1@4500.14,4050.09 ccw(c4483.92,4066.31) 4506.86,4066.31 ccw(c4529.79,4066.31) v1@4513.57,4050.09 ; v1@4502.97,4047.26 ccw(c4493.58,4056.65) 4506.86,4056.65 ccw(c4520.14,4056.65) v1@4510.75,4047.26 ; v1(4870.52,4833.37) 4890.94,4833.37 ; v1@4874.73,4829.83 cw(c4882.34,4823.43) 4882.34,4833.37 cw(c4882.34,4843.32) v1@4874.73,4836.92 ; v1@4877.79,4827.26 cw(c4890.94,4816.19) 4890.94,4833.37 ; v1@4877.79,4839.49 ccw(c4890.94,4850.56) 4890.94,4833.37 ; 4952.75,4724.74 4952.75,4720 ; v1@5542.81,3223.43 ccw(c5526.59,3239.64) 5549.52,3239.64 ccw(c5572.46,3239.64) v1@5556.24,3223.43 ; v1@5542.81,3252.66 cw(c5526.59,3236.44) 5549.52,3236.44 cw(c5572.46,3236.44) v1@5556.24,3252.66 ; v1@5545.64,3220.6 ccw(c5536.25,3229.99) 5549.52,3229.99 ccw(c5562.8,3229.99) v1@5553.41,3220.6 ; v1@5545.64,3255.49 cw(c5536.25,3246.1) 5549.52,3246.1 cw(c5562.8,3246.1) v1@5553.41,3255.49 ; v1(5549.52,3216.71) v1(5549.52,3259.37) ; 4890.94,4833.37 4895.31,4833.37 4952.75,4775.93 4952.75,4771.56 4952.75,4764 4952.75,4720 ; 4952.75,4720 4952.75,4710 4952.75,4643.27 ccw(c4962.9,4643.27) 4955.73,4636.09 4955.73,4635.87 4963.64,4627.95 ccw(c4976.61,4642.76) 4976.61,4623.07 cw(c4976.61,4603.38) 4996.3,4603.39 4996.3,4591.94 ccw(c5015.98,4591.94) 5002.06,4578.03 5002.06,4577.94 5003.45,4576.55 ; 5003.45,4576.55 cw(c4990.92,4564.02) 5008.64,4564.02 ccw(c4990.92,4564.02) 5003.45,4576.55 ; 5003.45,4576.55 ccw(c5015.98,4589.08) 5015.98,4571.36 cw(c5015.98,4589.08) 5003.45,4576.55
  MidLayer1 w4: 4476.41,4021.26 cw(c4506.86,3990.82) v1@4506.86,4033.87 ; 4483.24,4028.09 cw(c4506.86,4004.48) v1@4506.86,4037.87 ; 4490.07,4034.92 cw(c4506.86,4018.14) v1@4506.86,4041.87 ; v1(4506.86,4043.37) 4498.52,4043.37 4462.52,4007.37 4462.52,3702.71 4490.19,3675.04 4632.52,3675.04 4673.52,3634.04 4673.52,3575.04 4790.19,3458.37 4790.19,3375.04 v1(4856.86,3308.37) ; v1@4847.36,3308.37 ccw(c4824.42,3308.37) 4840.64,3324.59 ccw(c4856.86,3340.81) v1@4856.86,3317.87 ; v1@4851.36,3308.37 ccw(c4838.08,3308.37) 4847.47,3317.76 ccw(c4856.86,3327.15) v1@4856.86,3313.87
  MidLayer2 w4: v1(4181.86,4307.04) v1(4256.86,4307.04) ; v1@4185.75,4303.15 cw(c4195.14,4293.76) 4195.14,4307.04 cw(c4195.14,4320.32) v1@4185.75,4310.93 ; v1@4188.57,4300.32 cw(c4204.79,4284.11) 4204.79,4307.04 cw(c4204.79,4329.98) v1@4188.57,4313.76 ; v1@4250.14,4300.32 ccw(c4233.92,4284.11) 4233.92,4307.04 ccw(c4233.92,4329.98) v1@4250.14,4313.76 ; v1@4252.97,4303.15 ccw(c4243.58,4293.76) 4243.58,4307.04 ccw(c4243.58,4320.32) v1@4252.97,4310.93
  Bottom Layer w4: v1(4298.52,4833.37) v1(4870.52,4833.37) ; v1@4302.41,4829.49 cw(c4311.8,4820.1) 4311.8,4833.37 cw(c4311.8,4846.65) v1@4302.41,4837.26 ; v1@4305.24,4826.66 cw(c4321.46,4810.44) 4321.46,4833.37 cw(c4321.46,4856.31) v1@4305.24,4840.09 ; v1(4856.86,3308.37) 4910.84,3308.37 4973.84,3245.37 5110.5,3245.37 5139.17,3216.71 ; v1@4860.75,3304.49 cw(c4870.14,3295.1) 4870.14,3308.37 cw(c4870.14,3321.65) v1@4860.75,3312.26 ; v1@4863.57,3301.66 cw(c4879.79,3285.44) 4879.79,3308.37 cw(c4879.79,3331.31) v1@4863.57,3315.09 ; v1@4863.81,4826.66 ccw(c4847.59,4810.44) 4847.59,4833.37 ccw(c4847.59,4856.31) v1@4863.81,4840.09 ; v1@4866.64,4829.49 ccw(c4857.25,4820.1) 4857.25,4833.37 ccw(c4857.25,4846.65) v1@4866.64,4837.26 ; 5110.88,3245 5139.17,3216.71 ; v1(5549.52,3216.71) 5535,3231.23 5521.33,3231.23 5511.52,3241.04 5455.54,3241.04 5439.54,3225.04 5303.88,3225.04 5286.88,3208.04 5147.84,3208.04 5139.17,3216.71 ; v1(5549.52,3259.37) 5569,3259.37 5576.12,3266.5 5617.4,3266.5 5631.86,3252.04 5631.86,3221.37 5645.86,3207.37 5665,3207.37 5677.38,3195 R68.2@5705.82,3195 ; v1@5557.01,3253.53 cw(c5569,3244.17) 5569,3259.37 cw(c5569,3274.58) v1@5557.01,3265.22 ; R68.2@5699.23,3188.41 ccw(c5683.32,3172.5) 5683.32,3195 ccw(c5683.32,3217.5) R68.2@5699.23,3201.59 ; R68.2@5702.06,3191.24 ccw(c5692.98,3182.16) 5692.98,3195 ccw(c5692.98,3207.84) R68.2@5702.06,3198.76
TSC_3V3: NT42.1 U48.1 U48.9 U48.10 | length 4715.8
  Top Layer w4: v1@5658.47,2593.32 cw(c5642.26,2577.11) 5665.19,2577.11 cw(c5688.13,2577.11) v1@5671.91,2593.32 ; v1@5661.3,2596.15 cw(c5651.91,2586.76) 5665.19,2586.76 cw(c5678.47,2586.76) v1@5669.08,2596.15 ; v1(5665.19,2600.04) 5665.19,2508.37 5715.19,2458.37 5977.52,2458.37 6111.97,2592.82 6131.51,2592.82 6157.19,2618.5 6157.19,2642.04 6223.52,2708.37 ; v1@6234.51,2702.78 ccw(c6223.52,2694.79) 6223.52,2708.37 ; v1@6234.51,2713.97 cw(c6223.52,2721.96) 6223.52,2708.37 ; v1(6242.19,2708.37) 6223.52,2708.37 ; U48.1@6498.52,3169.57 U48.1@6497.8,3169.57 6559.33,3169.57 v1(6570.52,3158.37) ; U48.1@6527.83,3166.11 cw(c6536.17,3157.76) 6536.17,3169.57 cw(c6536.17,3181.37) U48.1@6527.83,3173.02 ; v1@6668.24,3005.01 ccw(c6663.88,3012.86) 6672.86,3012.86 ; v1@6673.92,2997.77 ccw(c6691.63,3015.48) U48.9@6691.63,2990.43 ; v1@6676.75,3000.6 ccw(c6701.28,3025.13) U48.9@6701.28,2990.43 ; v1@6677.47,3005.01 cw(c6681.83,3012.86) 6672.86,3012.86 ; v1@6679.57,3003.43 ccw(c6710.94,3034.79) U48.9@6710.94,2990.43 ; U48.9@6692.17,2986.98 ccw(c6683.83,2978.63) 6683.83,2990.43 ccw(c6683.83,3002.24) U48.9@6692.17,2993.89 ; U48.10@6692.17,3012.57 ccw(c6683.83,3004.22) 6683.83,3016.02 ccw(c6683.83,3027.83) U48.10@6692.17,3019.48 ; U48.9@6722.2,2990.43 6679.13,2990.43 v1(6672.86,2996.71) 6672.86,3012.86 ; U48.10@6722.2,3016.02 6676.02,3016.02 6672.86,3012.86
  MidLayer1 w4: v1@6232.69,2708.37 cw(c6209.76,2708.37) 6225.97,2692.16 cw(c6242.19,2675.94) v1@6242.19,2698.87 ; v1@6236.69,2708.37 cw(c6223.41,2708.37) 6232.8,2698.99 cw(c6242.19,2689.6) v1@6242.19,2702.87 ; v1(6242.19,2708.37) 6223.52,2689.71 6223.52,2557.71 6264.52,2516.71 6331.86,2516.71 6348.52,2533.37 6348.52,2583.37 6373.52,2608.37 6406.86,2608.37 6415.19,2616.71 6432.86,2616.71 6457.86,2591.71 6478.86,2591.71 6522.81,2635.66 6522.81,2662.38 6515.19,2670 6515.19,2816.71 6556.86,2858.37 6556.86,3070 6585,3098.14 6585,3143.9 v1(6570.52,3158.37)
  MidLayer2 w4: v1@4418.14,2515.09 ccw(c4401.92,2531.31) 4424.86,2531.31 ccw(c4447.79,2531.31) v1@4431.57,2515.09 ; v1@4420.97,2512.26 ccw(c4411.58,2521.65) 4424.86,2521.65 ccw(c4438.14,2521.65) v1@4428.75,2512.26 ; v1(4424.86,2508.37) 4424.86,2649.9 4450,2675.04 4939.79,2675.04 4981.46,2716.71 5153.21,2716.71 5178.54,2691.37 5235.17,2691.37 5243.84,2700.04 5487.21,2700.04 5545,2642.25 5545,2568.37 5555,2558.37 5623.52,2558.37 v1(5665.19,2600.04) ; v1@5655.69,2600.04 cw(c5632.76,2600.04) 5648.97,2583.82 cw(c5665.19,2567.61) v1@5665.19,2590.54 ; v1@5659.69,2600.04 cw(c5646.41,2600.04) 5655.8,2590.65 cw(c5665.19,2581.26) v1@5665.19,2594.54
  Bottom Layer w4: v1@4428.75,2504.49 cw(c4438.14,2495.1) 4438.14,2508.37 cw(c4438.14,2521.65) v1@4428.75,2512.26 ; v1@4431.57,2501.66 cw(c4447.79,2485.44) 4447.79,2508.37 cw(c4447.79,2531.31) v1@4431.57,2515.09 ; v1@4431.56,2508.37 cw(c4431.56,2474.71) NT42.1@4461.19,2490.7 ; 4438.27,2508.37 cw(c4438.27,2478.33) NT42.1@4464.71,2492.6 ; 4444.97,2508.37 cw(c4444.97,2481.95) NT42.1@4468.23,2494.5 ; 4451.68,2508.37 cw(c4451.68,2485.57) NT42.1@4471.75,2496.4 ; NT42.1@4457.67,2488.8 ccw(c4424.86,2471.1) v1(4424.86,2508.37) 4466.63,2508.37 4469.76,2505.24 NT42.1@4469.76,2485.08 NT42.1@4469.76,2483.37 ; NT42.1@4458.38,2508.37 cw(c4458.38,2489.19) NT42.1@4475.27,2498.3 ; v1@6570.52,3148.87 cw(c6570.52,3125.94) 6586.74,3142.16 cw(c6602.96,3158.37) v1@6580.02,3158.37 ; v1@6570.52,3152.87 cw(c6570.52,3139.6) 6579.91,3148.99 cw(c6589.3,3158.37) v1@6576.02,3158.37 ; v1(6570.52,3158.37) 6640.19,3088.71 6640.19,3029.37 v1(6672.86,2996.71) ; v1@6663.36,2996.71 ccw(c6640.42,2996.71) 6656.64,3012.93 ccw(c6672.86,3029.14) v1@6672.86,3006.21 ; v1@6667.36,2996.71 ccw(c6654.08,2996.71) 6663.47,3006.1 ccw(c6672.86,3015.49) v1@6672.86,3002.21
UIO_PWR.AIN: JP1.1 JP1.4 UH1.1 | length 680
  Bottom Layer w20: JP1.1@675.1,4713.08 JP1.4@775.1,4813.08 823.52,4813.08 923.37,4713.23 UH1.1@976.12,4713.23 ; JP1.1@675.1,4732.6 ccw(c675.1,4779.75) 708.43,4746.41 ccw(c741.77,4713.08) JP1.1@694.62,4713.08 ; JP1.4@755.57,4813.08 cw(c708.43,4813.08) 741.76,4779.74 cw(c775.1,4746.41) JP1.4@775.1,4793.55 ; JP1.4@788.91,4799.27 cw(c822.24,4765.93) 822.24,4813.08 cw(c822.24,4860.22) JP1.4@788.91,4826.89 ; UH1.1@962.31,4699.43 ccw(c928.98,4666.09) 928.98,4713.23 ccw(c928.98,4760.38) UH1.1@962.31,4727.04
UIO_PWR.BIN: JP2.1 JP2.4 UH2.1 | length 668.7
  Top Layer w20: JP2.1@2072.74,4713.08 JP2.4@2172.74,4813.08 2215.19,4813.08 ; JP2.1@2072.74,4732.6 ccw(c2072.74,4779.75) 2106.07,4746.41 ccw(c2139.41,4713.08) JP2.1@2092.26,4713.08 ; JP2.4@2153.21,4813.08 cw(c2106.06,4813.08) 2139.4,4779.74 cw(c2172.74,4746.41) JP2.4@2172.74,4793.55 ; JP2.4@2187.56,4800.37 cw(c2215.19,4776.69) 2215.19,4813.08 ; JP2.4@2187.56,4825.78 ccw(c2215.19,4849.46) 2215.19,4813.08 ; UH2.1@2359.95,4699.43 ccw(c2326.62,4666.09) 2326.62,4713.23 ccw(c2326.62,4760.38) UH2.1@2359.95,4727.04 ; UH2.1@2373.76,4713.23 2315.03,4713.23 2215.19,4813.08
USB_RSTA: R271.1 U56.42 U60.2 | length 1069.5
  Bottom Layer w4: U60.2@6044.34,5543.04 cw(c6041.46,5535) 6050,5535 cw(c6058.94,5535) U60.2@6055.57,5543.28 ; U60.2@6050,5570 6050,5535 6060,5525 6081.18,5525 R271.1@6111.18,5495 6281.86,5665.68 6281.86,5931.71 6283.52,5933.37 6406.86,5933.37 6448.52,5891.71 6473.52,5891.71 6482.05,5900.23 U56.42@6482.05,5980.67 ; 6094.43,5511.75 ccw(c6111.18,5528.5) 6111.18,5504.81 ccw(c6111.18,5528.5) 6127.93,5511.75 ; 6095.62,5510.56 cw(c6080.55,5495.49) R271.1@6101.86,5495.49 ; R271.1@6101.26,5504.92 ccw(c6111.18,5514.84) 6111.18,5500.81 ccw(c6111.18,5514.84) R271.1@6121.1,5504.92 ; R271.1@6102.45,5503.73 cw(c6094.21,5495.49) R271.1@6105.86,5495.49 ; R271.1@6116.5,5495.49 cw(c6128.15,5495.49) R271.1@6119.91,5503.73 ; R271.1@6120.5,5495.49 cw(c6141.81,5495.49) 6126.74,5510.56 ; U56.42@6479.22,5966.91 cw(c6472.39,5960.08) 6482.05,5960.08 cw(c6491.7,5960.08) U56.42@6484.88,5966.91
USB_RSTB: R248.1 U19.42 U49.2 | length 1346.2
  MidLayer2 w4: v1@7600.14,1430.32 ccw(c7583.92,1414.11) 7583.92,1437.04 ccw(c7583.92,1459.98) v1@7600.14,1443.76 ; v1@7602.97,1433.15 ccw(c7593.58,1423.76) 7593.58,1437.04 ccw(c7593.58,1450.32) v1@7602.97,1440.93 ; v1(7606.86,1437.04) 7507.04,1437.04 7481.86,1411.86 7481.86,1060 7496.86,1045 7585,1045 7615.19,1014.81 v1(7615.19,958.37) ; v1@7608.47,965.09 ccw(c7592.26,981.31) 7615.19,981.31 ccw(c7638.13,981.31) v1@7621.91,965.09 ; v1@7611.3,962.26 ccw(c7601.91,971.65) 7615.19,971.65 ccw(c7628.47,971.65) v1@7619.08,962.26
  Bottom Layer w4: U19.42@7547.95,904.33 7594.33,904.33 7615.19,925.19 v1(7615.19,958.37) ; U19.42@7550.78,901.5 cw(c7557.61,894.67) 7557.61,904.33 cw(c7557.61,913.99) U19.42@7550.78,907.16 ; v1(7606.86,1437.04) 7634.82,1465 7650,1465 7652.15,1467.15 ; v1@7606.86,1442.54 ccw(c7606.86,1455.82) 7616.25,1446.43 ccw(c7625.64,1437.04) v1@7612.36,1437.04 ; v1@7606.86,1446.54 ccw(c7606.86,1469.48) 7623.07,1453.26 ccw(c7639.29,1437.04) v1@7616.36,1437.04 ; v1@7608.47,951.66 cw(c7592.26,935.44) 7615.19,935.44 cw(c7638.13,935.44) v1@7621.91,951.66 ; v1@7611.3,954.49 cw(c7601.91,945.1) 7615.19,945.1 cw(c7628.47,945.1) v1@7619.08,954.49 ; U49.2@7642.96,1485.08 cw(c7630.04,1467.15) 7652.15,1467.15 ; U49.2@7645.3,1488.33 cw(c7635.67,1474.96) 7652.15,1474.96 cw(c7668.62,1474.96) U49.2@7658.99,1488.33 ; U49.2@7652.15,1506.69 7652.15,1467.15 ; U49.2@7661.33,1485.08 ccw(c7674.25,1467.15) 7652.15,1467.15 ; 7696.93,1456.75 ccw(c7713.68,1473.5) R248.1@7713.68,1449.81 ; 7698.12,1455.56 cw(c7683.05,1440.49) R248.1@7704.36,1440.49 ; R248.1@7703.76,1449.92 ccw(c7713.68,1459.84) R248.1@7713.68,1445.81 ; R248.1@7704.95,1448.73 cw(c7696.71,1440.49) R248.1@7708.36,1440.49 ; R248.1@7713.68,1440 7688.68,1465 7655,1465 7654.29,1465 7652.15,1467.15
